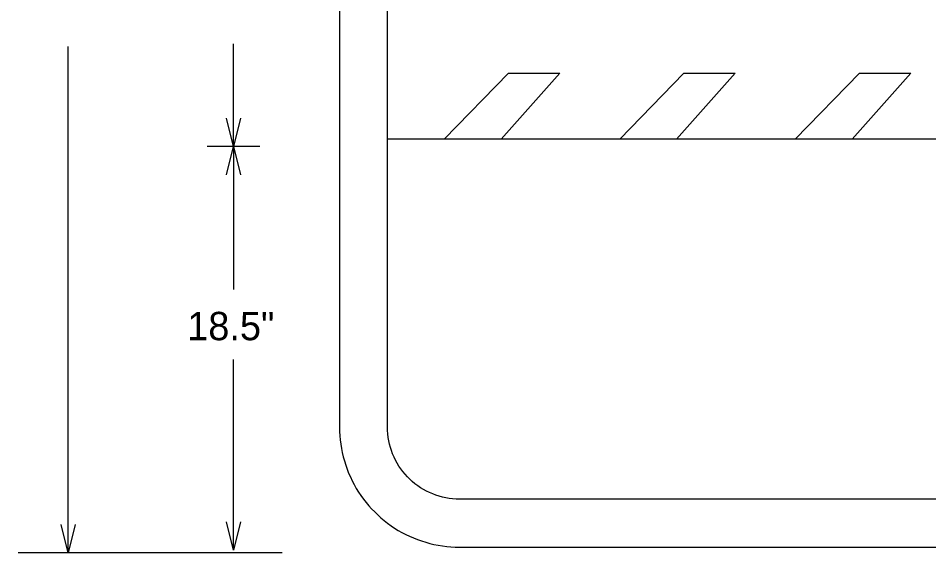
# Model space of a CAD drawing. Extents: x -2842 to 2681, y -2139 to 474.
# Drawn here: x 1111.5 to 1271.6, y -1762 to -1668 of the extents above; entities that cross this region are included whole.
import ezdxf

# ---------------------------------------------------------------- set-up
doc = ezdxf.new("R2010")
doc.units = 0
doc.layers.add('Default', color=7, linetype='Continuous')

msp = doc.modelspace()

# ---------------------------------------------------------------- linework, layer by layer
at = {"layer": 'Default'}
for p, q in [((1168.01, -1579.57), (1168.01, -1739.88)), ((1176.45, -1739.88), (1176.45, -1579.57)), ((1176.45, -1689.26), (1176.45, -1630.2)), ((1120.31, -1761.97), (1120.31, -1672.99)), ((1149.38, -1690.59), (1149.38, -1672.5)), ((1186.42, -1689.26), (1197.71, -1677.66)), ((1206.73, -1677.66), (1196.42, -1689.26)), ((1197.71, -1677.66), (1206.73, -1677.66)), ((1217.28, -1689.26), (1228.56, -1677.66)), ((1237.59, -1677.66), (1227.28, -1689.26)), ((1228.56, -1677.66), (1237.59, -1677.66)), ((1248.13, -1689.26), (1259.42, -1677.66)), ((1268.44, -1677.66), (1258.13, -1689.26)), ((1259.42, -1677.66), (1268.44, -1677.66)), ((1149.38, -1690.59), (1148.13, -1685.61)), ((1150.62, -1685.61), (1149.38, -1690.59)), ((1154.02, -1690.59), (1144.74, -1690.59)), ((1144.74, -1690.59), (1144.74, -1690.59)), ((1148.13, -1695.57), (1149.38, -1690.59)), ((1149.38, -1690.59), (1149.38, -1715.72)), ((1149.38, -1690.59), (1150.62, -1695.57)), ((1326.78, -1689.26), (1176.45, -1689.26)), ((1196.42, -1689.26), (1186.42, -1689.26)), ((1227.28, -1689.26), (1217.28, -1689.26)), ((1258.13, -1689.26), (1248.13, -1689.26)), ((1149.38, -1761.54), (1149.38, -1728.01)), ((1168.01, -1739.88), (1168.02, -1740.64)), ((1176.46, -1740.49), (1176.45, -1739.88)), ((1168.02, -1740.64), (1168.06, -1741.39)), ((1168.06, -1741.39), (1168.13, -1742.14)), ((1176.5, -1741.09), (1176.46, -1740.49)), ((1176.57, -1741.69), (1176.5, -1741.09)), ((1176.67, -1742.28), (1176.57, -1741.69)), ((1168.13, -1742.14), (1168.22, -1742.89)), ((1168.22, -1742.89), (1168.34, -1743.63)), ((1176.8, -1742.87), (1176.67, -1742.28)), ((1176.96, -1743.45), (1176.8, -1742.87)), ((1177.14, -1744.02), (1176.96, -1743.45)), ((1168.34, -1743.63), (1168.49, -1744.37)), ((1168.49, -1744.37), (1168.66, -1745.1)), ((1168.66, -1745.1), (1168.86, -1745.83)), ((1177.35, -1744.59), (1177.14, -1744.02)), ((1177.59, -1745.14), (1177.35, -1744.59)), ((1177.85, -1745.68), (1177.59, -1745.14)), ((1168.86, -1745.83), (1169.09, -1746.55)), ((1169.09, -1746.55), (1169.34, -1747.26)), ((1178.14, -1746.21), (1177.85, -1745.68)), ((1178.45, -1746.73), (1178.14, -1746.21)), ((1178.79, -1747.23), (1178.45, -1746.73)), ((1169.34, -1747.26), (1169.61, -1747.96)), ((1169.61, -1747.96), (1169.91, -1748.65)), ((1179.15, -1747.71), (1178.79, -1747.23)), ((1179.54, -1748.17), (1179.15, -1747.71)), ((1179.94, -1748.62), (1179.54, -1748.17)), ((1169.91, -1748.65), (1170.24, -1749.33)), ((1170.24, -1749.33), (1170.59, -1749.99)), ((1170.59, -1749.99), (1170.96, -1750.65)), ((1180.37, -1749.04), (1179.94, -1748.62)), ((1180.81, -1749.45), (1180.37, -1749.04)), ((1181.28, -1749.83), (1180.81, -1749.45)), ((1181.76, -1750.19), (1181.28, -1749.83)), ((1170.96, -1750.65), (1171.36, -1751.29)), ((1171.36, -1751.29), (1171.77, -1751.91)), ((1182.26, -1750.53), (1181.76, -1750.19)), ((1182.77, -1750.84), (1182.26, -1750.53)), ((1183.3, -1751.13), (1182.77, -1750.84)), ((1183.84, -1751.4), (1183.3, -1751.13)), ((1184.4, -1751.63), (1183.84, -1751.4)), ((1171.77, -1751.91), (1172.22, -1752.53)), ((1172.22, -1752.53), (1172.68, -1753.12)), ((1172.68, -1753.12), (1173.16, -1753.7)), ((1184.96, -1751.84), (1184.4, -1751.63)), ((1185.54, -1752.03), (1184.96, -1751.84)), ((1186.12, -1752.18), (1185.54, -1752.03)), ((1186.71, -1752.31), (1186.12, -1752.18)), ((1187.3, -1752.41), (1186.71, -1752.31)), ((1187.9, -1752.48), (1187.3, -1752.41)), ((1188.5, -1752.53), (1187.9, -1752.48)), ((1189.1, -1752.54), (1188.5, -1752.53)), ((1551.91, -1752.54), (1189.1, -1752.54)), ((1173.16, -1753.7), (1173.66, -1754.26)), ((1173.66, -1754.26), (1174.19, -1754.8)), ((1174.19, -1754.8), (1174.73, -1755.32)), ((1174.73, -1755.32), (1175.29, -1755.83)), ((1175.29, -1755.83), (1175.87, -1756.31)), ((1175.87, -1756.31), (1176.46, -1756.77)), ((1120.31, -1761.97), (1119.06, -1756.99)), ((1121.55, -1756.99), (1120.31, -1761.97)), ((1149.38, -1761.54), (1148.13, -1756.55)), ((1150.62, -1756.55), (1149.38, -1761.54)), ((1176.46, -1756.77), (1177.07, -1757.21)), ((1177.07, -1757.21), (1177.7, -1757.63)), ((1177.7, -1757.63), (1178.34, -1758.03)), ((1178.34, -1758.03), (1178.99, -1758.4)), ((1178.99, -1758.4), (1179.66, -1758.75)), ((1179.66, -1758.75), (1180.34, -1759.07)), ((1180.34, -1759.07), (1181.03, -1759.37)), ((1181.03, -1759.37), (1181.73, -1759.65)), ((1181.73, -1759.65), (1182.44, -1759.9)), ((1182.44, -1759.9), (1183.16, -1760.12)), ((1183.16, -1760.12), (1183.89, -1760.32)), ((1183.89, -1760.32), (1184.62, -1760.5)), ((1184.62, -1760.5), (1185.36, -1760.64)), ((1185.36, -1760.64), (1186.1, -1760.76)), ((1186.1, -1760.76), (1186.85, -1760.86)), ((1186.85, -1760.86), (1187.6, -1760.92)), ((1187.6, -1760.92), (1188.35, -1760.96)), ((1188.35, -1760.96), (1189.1, -1760.98)), ((1189.1, -1760.98), (1551.91, -1760.98)), ((1157.93, -1761.97), (1111.51, -1761.97)), ((1111.51, -1761.97), (1111.51, -1761.97))]:
    msp.add_line(p, q, dxfattribs=at)

# ---------------------------------------------------------------- texts
msp.add_text('18.5"', height=4.983, dxfattribs=at).set_placement((1141.23, -1724.61))

doc.saveas('drawing.dxf')
